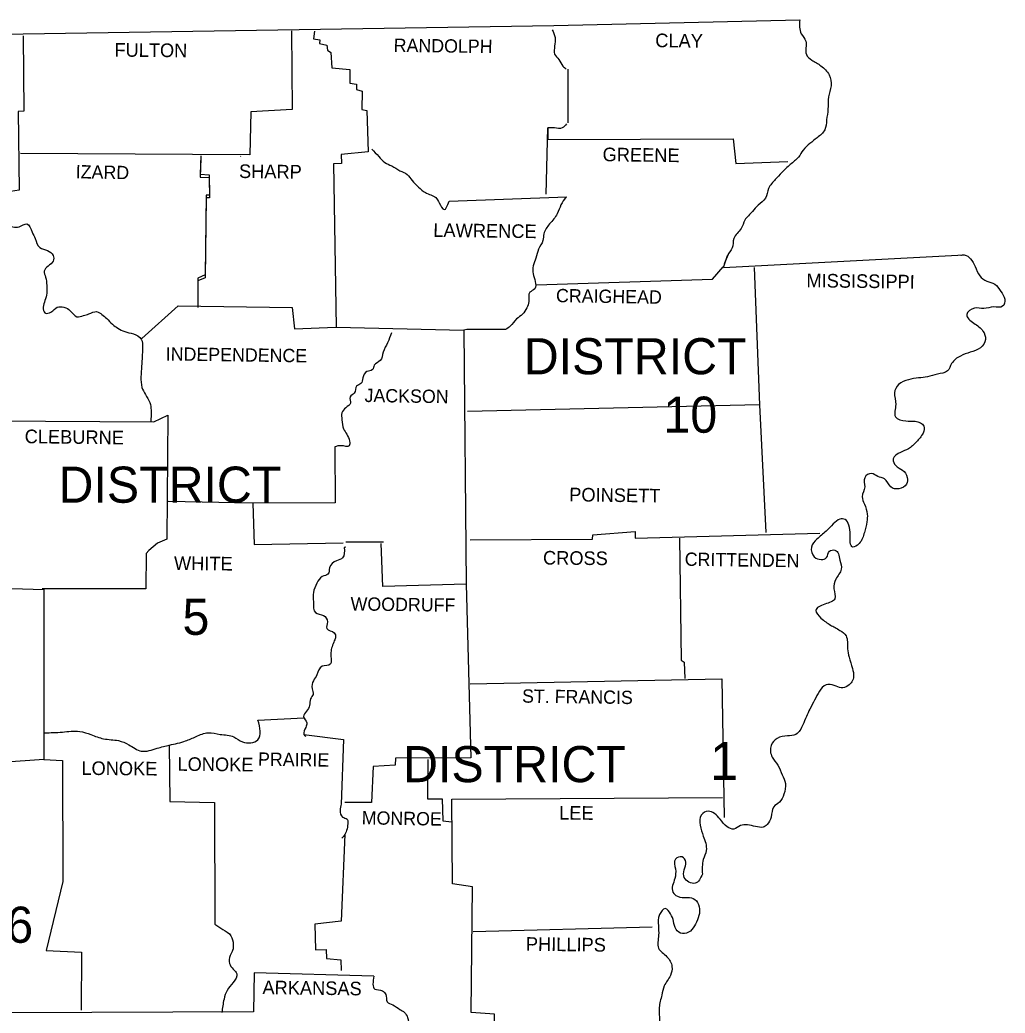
# Model space of a CAD drawing. Extents: x -17668 to 16999, y -17303 to 5867.
# Drawn here: x -16002 to -14292, y -8859 to -7133 of the extents above; entities that cross this region are included whole.
import ezdxf

# ---------------------------------------------------------------- set-up
doc = ezdxf.new("R2010")
doc.units = 0
for name, color, linetype in [('1', 7, 'Continuous'), ('2', 7, 'Continuous'), ('3', 7, 'Continuous')]:
    doc.layers.add(name, color=color, linetype=linetype)

msp = doc.modelspace()

# ---------------------------------------------------------------- linework, layer by layer
at = {"layer": '1'}
for p, q in [((-14780.6, -7563.1), (-14774, -7542.7)), ((-14779, -7556.5), (-14772.4, -7540.5)), ((-15436.7, -8039.7), (-15371.2, -8039.7))]:
    msp.add_line(p, q, dxfattribs=at)
for points in [[(-17667.8, -7158.5), (-16777.9, -7159.1), (-15996.9, -7157.4), (-15075.6, -7143.1), (-14648.6, -7133.2)], [(-15530.8, -7152.5), (-15529.7, -7289), (-15601.2, -7292.8), (-15603.4, -7367.7), (-16001.3, -7365.5)], [(-15491.2, -7153), (-15492.8, -7166.3), (-15481.8, -7167.9), (-15482.3, -7174.5), (-15469.7, -7177.3), (-15468.6, -7186.1), (-15462.5, -7189.9), (-15460.9, -7216.3), (-15429.5, -7219.6), (-15429.5, -7243.3), (-15418, -7245), (-15418, -7254.3), (-15408, -7257.1), (-15408.6, -7289), (-15399.8, -7290.6), (-15397.6, -7362.7), (-15444.4, -7367.1), (-15443.8, -7382.5), (-15458.1, -7383.1), (-15453.2, -7667.1), (-15231.4, -7672), (-15227.5, -8113.4), (-15372.3, -8117.3), (-15375, -8043)], [(-15996.9, -7160.7), (-15995.8, -7291.7), (-16005.2, -7292.3), (-16003.5, -7429.3), (-16042.1, -7434.8), (-16038.8, -7471.7), (-16025.5, -7488.8), (-16026.6, -7532.2), (-16101.5, -7535), (-16104.2, -7602.1), (-16172.5, -7604.3), (-16175.8, -7685.8), (-16171.9, -7692.4), (-16170.3, -7822.3), (-16052.5, -7830), (-16054.2, -8120), (-15960.6, -8122.8), (-15960.6, -8417.8), (-16034.4, -8423.3), (-16039.9, -8488.2), (-16163.7, -8488.8)], [(-15051.4, -7219.1), (-15051.4, -7312.1)], [(-15088.8, -7435.9), (-15086.1, -7320.9), (-15086.1, -7341.3), (-14764.1, -7339.6), (-14759.7, -7382.5), (-14668.9, -7379.2)], [(-15688.2, -7369.3), (-15689.3, -7401.3), (-15673.9, -7402.4), (-15673.3, -7437.6), (-15678.8, -7437.6), (-15681, -7576.3), (-15693.7, -7581.8), (-15693.7, -7628)], [(-15688.2, -7374.3), (-15689.3, -7406.2), (-15673.9, -7407.3), (-15673.3, -7442.5), (-15678.8, -7442.5), (-15681, -7581.2), (-15693.7, -7586.7), (-15693.7, -7633)], [(-15619.4, -7370.4), (-15618.8, -7369.9)], [(-15257.3, -7448), (-15053.1, -7440.9)], [(-14780.6, -7563.1), (-14362.9, -7541.6)], [(-15105.4, -7593.3), (-14799.9, -7583.4), (-14781.7, -7562.5)], [(-14727.8, -7563.6), (-14718.5, -7801.9), (-14707.4, -8023.7)], [(-15790.5, -7686.9), (-15727.8, -7630.2), (-15529.7, -7633), (-15525.8, -7669.8), (-15453.7, -7667.1)], [(-15159.3, -7670.9), (-15226.4, -7670.9), (-15231.4, -7672)], [(-14718.5, -7801.9), (-15225.3, -7813.5)], [(-16052.5, -7830), (-15769.6, -7831.6), (-15745.4, -7820.1), (-15747.1, -8035.3), (-15763.6, -8042.4), (-15778.4, -8055.1), (-15783.4, -8060), (-15783.9, -8121.7), (-15963.9, -8121.7)], [(-15455.9, -7875.1), (-15454.8, -7972), (-15597.9, -7972.5), (-15744.9, -7969.8)], [(-15597.9, -7972.5), (-15595.7, -8044.6), (-15441.1, -8041.9)], [(-15220.9, -8036.4), (-15008.5, -8035.3), (-15007.9, -8027.6), (-14934.2, -8022.1), (-14934.2, -8033.6), (-14613.9, -8024.8)], [(-14857.1, -8033.6), (-14854.4, -8245.5), (-14849.4, -8248.8), (-14847.8, -8277.4)], [(-15436.7, -8049), (-15439.4, -8049.6)], [(-15227.5, -8113.4), (-15219.3, -8415), (-15350.3, -8415.6), (-15350.8, -8427.7), (-15388.8, -8429.9), (-15392.1, -8492.6), (-15438.3, -8492.6)], [(-15220.9, -8286.8), (-14783.9, -8278)], [(-14783.9, -8278), (-14779.5, -8519)], [(-15589.1, -8349.5), (-15509.3, -8345.7)], [(-15509.3, -8374.3), (-15440.5, -8383.1), (-15444.4, -8495.4)], [(-15743.2, -8392.4), (-15742.1, -8491), (-15664.5, -8492.6), (-15664, -8703.9)], [(-15960.6, -8417.8), (-15928.7, -8420), (-15928.1, -8630.2), (-15956.8, -8749.6), (-15895.7, -8752.4), (-15896.2, -8853.6)], [(-15294.1, -8418.3), (-15294.7, -8486.6), (-15269.4, -8486.6), (-15268.3, -8524.5), (-15252.3, -8526.2)], [(-15220.9, -8974.7), (-15178, -8972), (-15178.6, -8860.2), (-15218.7, -8857.5), (-15216.5, -8639), (-15251.2, -8634), (-15252.3, -8487.1), (-14782.8, -8483.8)], [(-15438.3, -8548.2), (-15444.9, -8699), (-15490.1, -8703.9), (-15489, -8748.5), (-15470.8, -8748), (-15470.2, -8763.4), (-15445.5, -8766.1), (-15444.9, -8784.3)], [(-15215.4, -8716.6), (-14905, -8708.9)], [(-15387.7, -8794.2), (-15595.7, -8788.7), (-15596.8, -8856.4), (-16017.8, -8858)]]:
    msp.add_lwpolyline(points, dxfattribs=at)
for points in [[(-14648.6, -7133.2), (-14645.8, -7157.4), (-14638.1, -7170.1), (-14637, -7193.2), (-14627.6, -7203.1), (-14611.7, -7213), (-14597.4, -7229), (-14594.1, -7247.7), (-14598.5, -7267), (-14599.6, -7288.4), (-14601.8, -7307.1), (-14605.1, -7324.2), (-14618.3, -7338), (-14630.9, -7347.9), (-14642.5, -7359.4), (-14650.8, -7371.5), (-14665.1, -7384.7), (-14679.4, -7398.5), (-14690.9, -7410.6), (-14702.5, -7426), (-14708, -7443.1), (-14720.7, -7455.2), (-14730.6, -7466.2), (-14743.8, -7481.1), (-14750.4, -7495.9), (-14763, -7513), (-14765.8, -7529.5), (-14774, -7542.7), (-14774.6, -7544.9)], [(-15078.4, -7150.3), (-15073.4, -7164.1), (-15074, -7178.9), (-15074, -7192.7), (-15066.8, -7202), (-15059.7, -7213.6), (-15054.2, -7218.5)], [(-15053.6, -7313.7), (-15060.8, -7320.9), (-15074.5, -7320.9), (-15086.1, -7320.9)], [(-15391.5, -7357.8), (-15379.4, -7370.4), (-15369, -7380.9), (-15356.9, -7386.9), (-15342.6, -7395.2), (-15329.9, -7401.8), (-15321.6, -7412.3), (-15310.1, -7423.8), (-15298.5, -7433.2), (-15280.4, -7442), (-15274.3, -7451.3), (-15266.1, -7462.9), (-15257.3, -7448)], [(-15054.7, -7441.4), (-15063, -7454.6), (-15069.6, -7470), (-15082.8, -7487.7), (-15092.7, -7504.7), (-15094.3, -7516.3), (-15102.1, -7531.7), (-15106.5, -7547.1), (-15111.4, -7560.3), (-15111.4, -7574.1), (-15107.6, -7587.8), (-15108.7, -7600.5), (-15116.9, -7606.5), (-15119.1, -7622.5), (-15122.4, -7633.5), (-15129.6, -7644.5), (-15140, -7652.8), (-15151, -7665.4), (-15159.3, -7670.9)], [(-16025.5, -7488.8), (-16003.5, -7492.6), (-15990.3, -7487.7), (-15981, -7502), (-15976, -7513), (-15967.8, -7528.9), (-15954.6, -7533.9), (-15944.6, -7542.7), (-15944.6, -7552.1), (-15953.4, -7560.9), (-15960.1, -7569.7), (-15957.9, -7580.1), (-15955.7, -7594.4), (-15955.7, -7608.2), (-15959, -7620.8), (-15961.7, -7632.4), (-15959, -7642.3), (-15948.5, -7640.7), (-15937.5, -7632.4), (-15925.9, -7632.4), (-15914.9, -7638.5), (-15903.4, -7648.9), (-15891.8, -7646.7), (-15882.5, -7644), (-15869.2, -7640.1), (-15859.9, -7645.1), (-15851.6, -7651.7), (-15841.7, -7662.1), (-15832.4, -7668.7), (-15820.3, -7674.8), (-15805.4, -7678.6), (-15791.6, -7688), (-15789.4, -7703.9), (-15790, -7717.7), (-15791.1, -7734.8), (-15792.2, -7753.5), (-15790.5, -7771.6), (-15784.5, -7783.8), (-15776.8, -7798.1), (-15774.6, -7811.3), (-15775.1, -7832.2)], [(-14369, -7542.1), (-14362.9, -7541.6), (-14344.2, -7561.4), (-14336, -7577.9), (-14323.9, -7587.3), (-14310.1, -7592.2), (-14299.6, -7604.9), (-14292.5, -7618.6), (-14296.3, -7630.8), (-14311.7, -7631.9), (-14328.8, -7634.6), (-14345.3, -7634.1), (-14358.5, -7645.1), (-14346.4, -7659.9), (-14330.5, -7673.7), (-14326.1, -7688.5), (-14334.9, -7702.8), (-14352.5, -7710.6), (-14369.5, -7717.2), (-14384.9, -7730.4), (-14392.1, -7743), (-14409.2, -7748.5), (-14426.8, -7753.5), (-14442.2, -7755.1), (-14459.8, -7758.4), (-14476.9, -7766.7), (-14484, -7781), (-14481.8, -7801.4), (-14482.4, -7822.8), (-14464.2, -7830), (-14448.2, -7830.5), (-14432.8, -7838.8), (-14434.5, -7850.9), (-14446, -7866.3), (-14459.8, -7878.4), (-14473.5, -7884.5), (-14486.2, -7896), (-14481.8, -7907.6), (-14470.2, -7915.3), (-14462, -7927.9), (-14463.1, -7939.5), (-14476.3, -7947.8), (-14490.6, -7944.5), (-14501.1, -7930.7), (-14513.2, -7926.3), (-14523.6, -7921.3), (-14535.7, -7928.5), (-14535.7, -7944.5), (-14540.1, -7961.5), (-14536.3, -7974.2), (-14531.3, -7991.8), (-14531.9, -8005), (-14536.3, -8023.7), (-14545.6, -8043), (-14556.7, -8049), (-14561.1, -8028.1), (-14563.3, -8011), (-14569.9, -8001.1), (-14578.7, -8000.6), (-14590.2, -8008.8), (-14602.9, -8021.5), (-14618.8, -8035.3), (-14628.2, -8049), (-14623.2, -8066.1), (-14611.1, -8070.5), (-14601.8, -8067.2), (-14596.8, -8056.2), (-14587.5, -8054.5), (-14578.7, -8071.6)], [(-15357.4, -7677), (-15364, -7694), (-15371.7, -7710.6), (-15376.7, -7724.9), (-15387.1, -7733.1), (-15390.4, -7740.8), (-15399.8, -7744.1), (-15406.9, -7755.1), (-15410.3, -7765), (-15418, -7769.4), (-15421.8, -7781.5), (-15429, -7788.2), (-15428.4, -7799.2), (-15436.7, -7806.9), (-15443.3, -7815.7), (-15443.3, -7827.8), (-15440.5, -7843.7), (-15435, -7853.1), (-15430.1, -7865.2), (-15430.6, -7872.9), (-15444.4, -7872.9), (-15455.9, -7875.1)], [(-15439.4, -8049.6), (-15442.2, -8067.7), (-15452.6, -8072.7), (-15464.7, -8084.8), (-15467.5, -8095.8), (-15477.4, -8100.2), (-15486.7, -8111.8), (-15492.8, -8127.7), (-15492.8, -8144.2), (-15489, -8162.9), (-15475.2, -8167.9), (-15468.6, -8178.9), (-15469.7, -8190.5), (-15456.5, -8198.2), (-15454.3, -8204.8), (-15456.5, -8211.9), (-15462.5, -8232.3), (-15462, -8246), (-15463.1, -8252.1), (-15477.9, -8256), (-15486.7, -8270.8), (-15492.8, -8281.3), (-15495, -8295), (-15493.4, -8304.9), (-15497.8, -8312.6), (-15499.4, -8324.2), (-15504.9, -8334.1), (-15509.9, -8343.5), (-15504.4, -8354.5), (-15506, -8362.2), (-15509.3, -8374.3), (-15506.6, -8378.1)], [(-14578.7, -8071.6), (-14576.5, -8087.5), (-14585.8, -8104.6), (-14589.1, -8121.7), (-14587.5, -8138.7), (-14605.1, -8148.1), (-14620.5, -8159.1), (-14611.7, -8172.3), (-14595.2, -8184.4), (-14578.7, -8193.8), (-14568.2, -8203.1), (-14565.5, -8225.7), (-14562.7, -8240), (-14557.2, -8259.8), (-14555, -8273.6), (-14564.9, -8290.1), (-14576.5, -8293.4), (-14588.6, -8289.5), (-14602.9, -8288.4), (-14614.4, -8299.4), (-14622.7, -8314.8), (-14630.9, -8330.3), (-14637, -8343.5), (-14643.1, -8357.8), (-14655.2, -8374.3), (-14670, -8377), (-14687.6, -8381.4), (-14698.1, -8393.5), (-14696.4, -8413.9), (-14686.5, -8427.7), (-14678.8, -8444.7), (-14673.3, -8459.6), (-14676.1, -8478.3), (-14683.8, -8492.1), (-14693.7, -8500.3), (-14698.1, -8517.9), (-14705.2, -8531.1), (-14711.9, -8535.5), (-14725.1, -8534.4), (-14739.4, -8531.7), (-14751.5, -8532.8), (-14763, -8538.8), (-14774.6, -8535), (-14786.7, -8521.8), (-14796.6, -8511.9), (-14807.6, -8508), (-14819.2, -8514.1), (-14821.4, -8532.2), (-14815.9, -8550.9), (-14810.9, -8576.3), (-14815.9, -8591.7), (-14817.5, -8617)], [(-15959.5, -8371.5), (-15928.7, -8370.4), (-15898.4, -8369.3), (-15879.2, -8374.8), (-15857.1, -8382), (-15831.3, -8385.3), (-15813.1, -8392.4), (-15791.6, -8403.4), (-15764.1, -8398.5), (-15742.7, -8393), (-15714.6, -8385.8), (-15696.4, -8378.1), (-15675.5, -8371.5), (-15654.6, -8374.3), (-15630.9, -8378.7), (-15616.1, -8387.5), (-15589.1, -8383.6), (-15589.1, -8349.5)], [(-15444.4, -8495.4), (-15446.6, -8506.4), (-15442.2, -8517.9), (-15434.5, -8521.8), (-15433.4, -8532.8), (-15436.1, -8543.8), (-15438.3, -8548.2), (-15443.3, -8554.8)], [(-14817.5, -8617), (-14830.2, -8632.9), (-14848.9, -8623), (-14848.9, -8609.8), (-14846.1, -8596.1), (-14852.7, -8587.3), (-14864.3, -8591.1), (-14864.3, -8608.2), (-14865.4, -8624.7), (-14868.7, -8648.4), (-14861, -8655.5), (-14843.4, -8657.7), (-14830.7, -8661), (-14823, -8673.7), (-14823.6, -8689.1), (-14829.6, -8703.9), (-14838.4, -8716), (-14852.2, -8720.5), (-14863.2, -8713.3), (-14867.6, -8699), (-14872.6, -8686.3), (-14881.9, -8677), (-14891.8, -8687.4), (-14894, -8706.7), (-14893.5, -8723.2), (-14893.5, -8745.8), (-14879.2, -8760.6), (-14870.4, -8777.7), (-14873.1, -8793.1), (-14883.6, -8811.3), (-14888, -8827.2), (-14892.4, -8848.7), (-14891.8, -8872.3), (-14895.7, -8895.5), (-14903.4, -8910.9), (-14917.7, -8923.5), (-14927, -8931.8), (-14934.7, -8940), (-14938.6, -8956.6), (-14941.3, -8968.1), (-14951.8, -8981.9), (-14960.1, -8983), (-14966.7, -8977.5), (-14968.9, -8968.1), (-14968.9, -8958.8), (-14973.3, -8949.4), (-14987, -8945.5), (-14998, -8946.1), (-15003, -8953.8), (-14995.8, -8975.3), (-14993.1, -8989), (-14996.9, -9007.7), (-14994.7, -9009.9), (-15014.5, -9020.4), (-15030.5, -9022), (-15043.7, -9025.9), (-15056.4, -9034.2), (-15062.4, -9046.3), (-15071.2, -9056.2), (-15078.9, -9065.5), (-15089.4, -9069.9), (-15101, -9067.7), (-15116.4, -9066.1), (-15125.2, -9077.1), (-15122.4, -9093), (-15112, -9102.4), (-15096.5, -9106.8), (-15080.6, -9105.7), (-15065.2, -9104), (-15050.9, -9111.8), (-15053.6, -9126.6), (-15067.4, -9133.8), (-15087.7, -9136), (-15104.3, -9134.3), (-15124.1, -9138.7), (-15134, -9151.4), (-15128.5, -9170.6), (-15107, -9178.3), (-15097.1, -9196.5), (-15096.5, -9213.6), (-15103.7, -9236.1), (-15113.6, -9246.6), (-15132.9, -9251), (-15147.7, -9253.7), (-15149.9, -9279.1), (-15156.5, -9291.7), (-15168.1, -9295.6), (-15184.6, -9287.3), (-15194.5, -9283.5), (-15206.6, -9278), (-15222, -9268.6), (-15233.6, -9270.3), (-15230.3, -9294.5), (-15229.2, -9295.6), (-15216, -9313.7), (-15202.8, -9328), (-15196.7, -9345.1)], [(-15664, -8703.9), (-15650.2, -8713.3), (-15635.9, -8724.3), (-15632, -8739.2), (-15633.1, -8749.6), (-15637.5, -8758.4), (-15638.6, -8772.2), (-15632, -8782.1), (-15626, -8790.3), (-15632, -8805.2), (-15642.5, -8819), (-15648, -8834.4), (-15651.9, -8857.5)], [(-15387.7, -8794.2), (-15386, -8816.8), (-15372.8, -8820.1), (-15367.3, -8826.1), (-15364.6, -8838.8), (-15355.2, -8844.3), (-15342.6, -8852), (-15334.9, -8857.5), (-15329.3, -8866.3), (-15326, -8880.6), (-15317.2, -8890), (-15305.1, -8894.4), (-15296.3, -8904.8), (-15290.8, -8919.7), (-15282, -8926.3), (-15273.2, -8937.8), (-15268.8, -8942.8), (-15261.1, -8956), (-15253.4, -8962.6), (-15247.9, -8966.5), (-15239.1, -8969.2), (-15228.1, -8976.4), (-15220.9, -8987.4), (-15220.9, -8995.6), (-15223.7, -9008.3), (-15225.9, -9021.5), (-15227, -9036.4), (-15228.1, -9049.6), (-15223.1, -9060.6), (-15225.9, -9077.1), (-15231.4, -9085.9), (-15231.9, -9098), (-15233.6, -9116.2), (-15235.8, -9126.6), (-15240.7, -9143.7), (-15247.9, -9152.5)]]:
    msp.add_spline(points, degree=3, dxfattribs=at)

# ---------------------------------------------------------------- texts
msp.add_text('1', height=66, dxfattribs=at).set_placement((-14804.3, -8453.5))
at = {"layer": '2'}
for s, height, rotation, p in [('CLAY', 23.66, 359.2258, (-14899.5, -7180.6)), ('FULTON', 23.66, 359.4996, (-15838.4, -7197.1)), ('RANDOLPH', 23.11, 359.2583, (-15353.6, -7188.8)), ('GREENE', 23.67, 359.2361, (-14990.9, -7378.7)), ('SHARP', 23.66, 359.3905, (-15622.1, -7407.9)), ('IZARD', 23.11, 358.9258, (-15905.6, -7408.4)), ('LAWRENCE', 23.67, 359.2678, (-15284.8, -7510.2)), ('MISSISSIPPI', 23.66, 359.3097, (-14637, -7597.7)), ('CRAIGHEAD', 23.11, 359.1159, (-15071.8, -7623.6)), ('INDEPENDENCE', 23.108, 359.2187, (-15749.3, -7724.9)), ('JACKSON', 23.11, 359.1352, (-15404.2, -7797)), ('CLEBURNE', 23.66, 359.2535, (-15994.2, -7868.5)), ('POINSETT', 23.66, 359.1987, (-15048.8, -7969.5)), ('CROSS', 23.66, 359.3839, (-15094.3, -8079.3)), ('WHITE', 23.67, 359.3139, (-15735, -8088.6)), ('CRITTENDEN', 23.11, 359.213, (-14848.3, -8081.5)), ('WOODRUFF', 23.11, 359.2748, (-15428.4, -8159.1)), ('ST. FRANCIS', 23.108, 359.2216, (-15130.7, -8319.2)), ('LONOKE', 23.67, 359.4974, (-15728.9, -8437.6)), ('PRAIRIE', 23.11, 359.2116, (-15589.1, -8428.8)), ('LONOKE', 23.67, 359.4974, (-15895.7, -8444.7)), ('LEE', 23.67, 359.4327, (-15066.3, -8522.3)), ('MONROE', 23.11, 359.0331, (-15409.1, -8530.6)), ('PHILLIPS', 23.66, 359.3179, (-15124.1, -8750.2)), ('ARKANSAS', 23.66, 359.2678, (-15581.4, -8825.6))]:
    msp.add_text(s, height=height, rotation=rotation, dxfattribs=at).set_placement(p)
at = {"layer": '3'}
for s, height, p in [('DISTRICT', 62.74, (-15127.6, -7748.9)), ('10', 62.74, (-14885.1, -7850.4)), ('DISTRICT', 62.74, (-15935.3, -7972)), ('5', 62.7, (-15720.1, -8201.5)), ('DISTRICT', 62.74, (-15337.1, -8457.4)), ('DISTRICT 6', 62.74, (-16436.1, -8736.4))]:
    msp.add_text(s, height=height, dxfattribs=at).set_placement(p)

doc.saveas('drawing.dxf')
